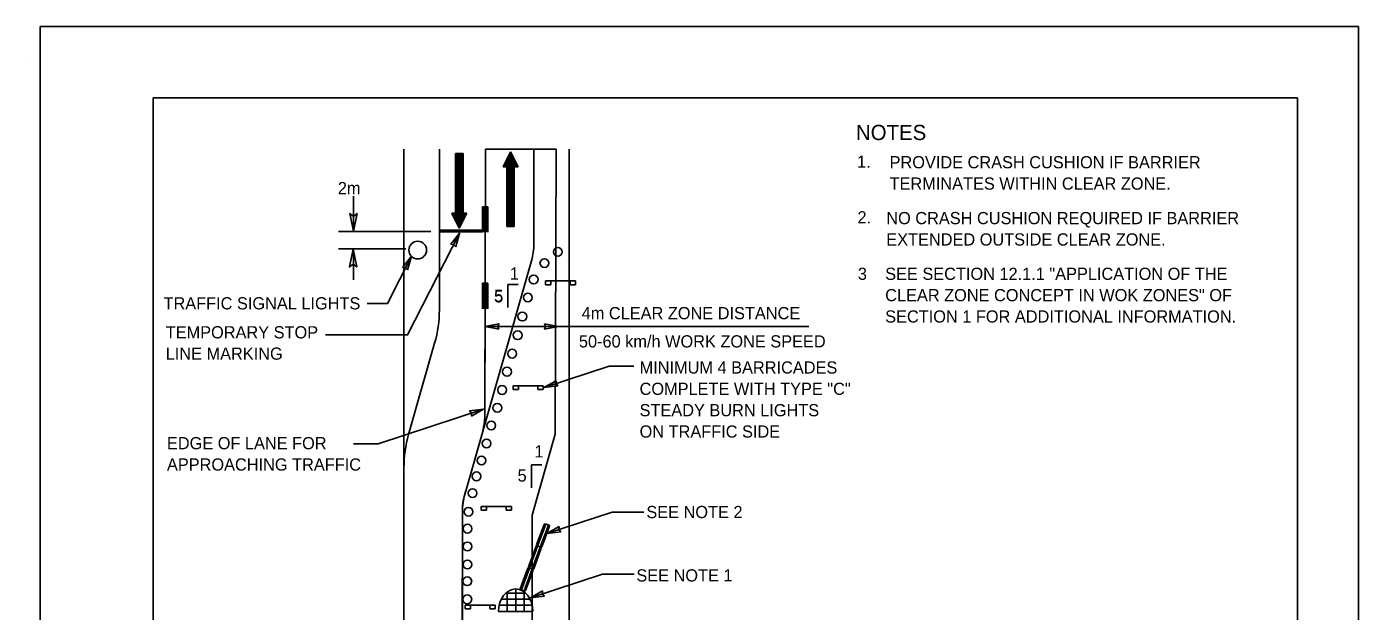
# Model space of a CAD drawing. Extents: x 2427 to 2645, y -255 to 24.
# Drawn here: x 2426.8 to 2645, y -71.9 to 24 of the extents above; entities that cross this region are included whole.
import ezdxf

# ---------------------------------------------------------------- set-up
doc = ezdxf.new("R2010")
doc.units = 0
for name, color, linetype in [('Level 10', 7, 'Continuous'), ('Level 17', 7, 'Continuous'), ('Level 22', 7, 'Continuous'), ('Level 4', 7, 'Continuous'), ('Level 44', 7, 'Continuous'), ('Level 5', 7, 'Continuous'), ('Level 60', 7, 'Continuous')]:
    doc.layers.add(name, color=color, linetype=linetype)

# ---------------------------------------------------------------- blocks, each defined once
blk = doc.blocks.new('TAH01')
at = {"layer": 'Level 5'}
blk.add_lwpolyline([(0, 0), (-3, -0.62), (-2.504, 0), (-3, 0.62)], close=True, dxfattribs=at)
blk = doc.blocks.new('LT1')
at = {"layer": 'Level 5'}
blk.add_blockref('TAH01', (0, 0), dxfattribs=at)
blk = doc.blocks.new('arrow')
at = {"layer": 'Level 60'}
blk.add_lwpolyline([(0.6, 0.12), (0, 0), (0.6, -0.12), (0.56, 0)], close=True, dxfattribs=at)

msp = doc.modelspace()

# ---------------------------------------------------------------- linework, layer by layer
at = {"layer": 'Level 10'}
for p, q in [((2488.59, 3.9), (2488.59, -74.14)), ((2494.4, 3.9), (2494.4, -22.41)), ((2497.05, -6.58), (2497.05, 3.23)), ((2497.05, 3.23), (2498.28, 3.23)), ((2497.05, -7.81), (2497.05, 3.23)), ((2497.21, -8.12), (2497.21, 3.23)), ((2497.36, -8.42), (2497.36, 3.23)), ((2497.52, -8.73), (2497.52, 3.23)), ((2497.67, -9.04), (2497.67, 3.23)), ((2497.82, -8.73), (2497.82, 3.23)), ((2497.97, -8.42), (2497.97, 3.23)), ((2498.13, -8.12), (2498.13, 3.23)), ((2498.28, -6.58), (2498.28, 3.23)), ((2498.28, -7.81), (2498.28, 3.23)), ((2506.06, 3.5), (2504.84, 1.05)), ((2505.45, 2.28), (2505.45, -8.77)), ((2505.61, 2.58), (2505.61, -8.77)), ((2505.76, 2.89), (2505.76, -8.77)), ((2505.91, 3.19), (2505.91, -8.77)), ((2506.06, 3.5), (2506.06, -8.77)), ((2506.06, 3.5), (2507.29, 1.05)), ((2506.22, 3.19), (2506.22, -8.77)), ((2506.37, 2.89), (2506.37, -8.77)), ((2506.53, 2.58), (2506.53, -8.77)), ((2506.68, 2.28), (2506.68, -8.77)), ((2509.88, 3.9), (2509.88, -11.62)), ((2515.69, 3.9), (2515.69, -98.92)), ((2505.45, 1.05), (2504.84, 1.05)), ((2504.99, 1.35), (2504.99, 1.05)), ((2505.15, 1.66), (2505.15, 1.05)), ((2505.3, 1.97), (2505.3, 1.05)), ((2505.45, 1.05), (2505.45, -8.77)), ((2506.68, 1.05), (2506.68, -8.77)), ((2507.29, 1.05), (2506.68, 1.05)), ((2506.83, 1.97), (2506.83, 1.05)), ((2506.99, 1.66), (2506.99, 1.05)), ((2507.14, 1.35), (2507.14, 1.05)), ((2480.31, -3.77), (2480.31, -9.53)), ((2497.67, -9.04), (2496.44, -6.58)), ((2496.44, -6.58), (2497.05, -6.58)), ((2496.59, -6.89), (2496.59, -6.58)), ((2496.75, -7.2), (2496.75, -6.58)), ((2496.9, -7.5), (2496.9, -6.58)), ((2497.67, -9.04), (2498.89, -6.58)), ((2498.28, -6.58), (2498.89, -6.58)), ((2498.43, -7.5), (2498.43, -6.58)), ((2498.59, -7.2), (2498.59, -6.58)), ((2498.74, -6.89), (2498.74, -6.58)), ((2493.03, -9.56), (2477.87, -9.56)), ((2494.4, -9.35), (2501.48, -9.35)), ((2494.4, -9.45), (2501.48, -9.45)), ((2494.4, -9.45), (2501.48, -9.45)), ((2494.4, -9.55), (2501.48, -9.55)), ((2494.4, -9.55), (2501.48, -9.55)), ((2494.4, -9.55), (2501.48, -9.55)), ((2494.4, -9.64), (2501.48, -9.64)), ((2494.4, -9.64), (2501.48, -9.64)), ((2506.68, -8.77), (2505.45, -8.77)), ((2488.92, -12.43), (2477.87, -12.43)), ((2480.31, -12.6), (2480.31, -17.5)), ((2509.5, -14.36), (2498.57, -52.7)), ((2501.86, -39.8), (2501.9, -22.24)), ((2493.63, -27.89), (2489.37, -42.86)), ((2498.79, -51.93), (2501.47, -42.52)), ((2513.4, -42.82), (2509.61, -56.11)), ((2488.6, -172.56), (2488.6, -48.35)), ((2498.24, -172.68), (2498.19, -55.44))]:
    msp.add_line(p, q, dxfattribs=at)
for points in [[(2501.97, 3.9), (2513.52, 3.9), (2513.4, -42.82), (2509.61, -56.11), (2509.63, -98.92), (2498.08, -98.91), (2498.19, -55.44)], [(2501.47, -42.52), (2501.79, -40.85), (2501.86, -39.8), (2501.97, 3.9)]]:
    msp.add_lwpolyline(points, dxfattribs=at)
for centre in [(2513.82, -12.91), (2511.61, -14.76), (2509.85, -17.45), (2508.9, -20.41), (2508, -23.53), (2507.23, -26.59), (2506.33, -29.61), (2505.49, -32.56), (2504.68, -35.57), (2503.9, -38.48), (2502.91, -41.39), (2502.14, -44.33), (2501.3, -47.12), (2500.48, -49.72), (2499.85, -52.47), (2499.17, -55.52), (2499.01, -58.3), (2499, -61.21), (2499, -64.17), (2498.98, -66.92), (2498.98, -69.88)]:
    msp.add_circle(centre, 0.718, dxfattribs=at)
for centre, radius, start, end in [((2499.88, -11.62), 10, 344.0903, 0), ((2474.4, -22.41), 20, 344.0903, 360), ((2491.86, -39.78), 10, 344.0903, 359.8496), ((2508.6, -48.35), 20, 164.0903, 180), ((2507.62, -55.25), 9.43, 159.4198, 181.1903), ((2508.19, -55.44), 10, 164.0903, 180.023)]:
    msp.add_arc(centre, radius, start, end, dxfattribs=at)
at = {"layer": 'Level 17'}
for p, q in [((2428.98, 24.01), (2644.98, 24.01)), ((2428.98, -254.99), (2428.98, 24.01)), ((2644.98, 24.01), (2644.98, -254.99))]:
    msp.add_line(p, q, dxfattribs=at)
at = {"layer": 'Level 22'}
for p, q in [((2447.52, 12.32), (2447.52, -244.18)), ((2447.52, 12.32), (2634.98, 12.32)), ((2634.98, 12.32), (2634.98, -244.18))]:
    msp.add_line(p, q, dxfattribs=at)
at = {"layer": 'Level 4'}
for p, q in [((2511.58, -57.6), (2510.34, -60.95)), ((2510.51, -61.15), (2511.84, -57.55)), ((2510.94, -61.31), (2512.27, -57.71)), ((2511.2, -61.27), (2512.44, -57.91)), ((2511.75, -57.52), (2511.58, -57.6)), ((2512.37, -57.75), (2511.75, -57.52)), ((2512.44, -57.91), (2512.37, -57.75)), ((2510.34, -60.95), (2510.41, -61.12)), ((2510.24, -61.19), (2509, -64.55)), ((2509.18, -64.75), (2510.51, -61.15)), ((2509.61, -64.91), (2510.94, -61.31)), ((2509.87, -64.87), (2511.11, -61.51)), ((2510.41, -61.12), (2510.24, -61.19)), ((2511.03, -61.35), (2510.41, -61.12)), ((2510.41, -61.12), (2511.04, -61.34)), ((2511.11, -61.51), (2511.03, -61.35)), ((2511.2, -61.27), (2511.04, -61.34)), ((2508.91, -64.79), (2507.67, -68.15)), ((2507.84, -68.35), (2509.17, -64.75)), ((2508.28, -68.51), (2509.6, -64.91)), ((2508.54, -68.46), (2509.78, -65.11)), ((2509.08, -64.71), (2508.91, -64.79)), ((2509, -64.55), (2509.08, -64.71)), ((2509.7, -64.94), (2509.08, -64.71)), ((2509.08, -64.71), (2509.7, -64.94)), ((2509.87, -64.87), (2509.7, -64.94)), ((2509.78, -65.11), (2509.7, -64.94)), ((2505.29, -68.86), (2508.54, -68.86)), ((2505.52, -71.86), (2505.52, -68.67)), ((2506.92, -71.86), (2506.92, -68.18)), ((2507.67, -68.15), (2507.75, -68.31)), ((2507.75, -68.31), (2508.37, -68.54)), ((2508.32, -71.86), (2508.32, -68.67)), ((2508.54, -68.46), (2508.37, -68.54)), ((2504.11, -71.86), (2509.72, -71.86)), ((2504.22, -70.86), (2509.62, -70.86)), ((2504.56, -69.86), (2509.27, -69.86))]:
    msp.add_line(p, q, dxfattribs=at)
msp.add_ellipse((2506.92, -71.88), major_axis=(0, 3.7), ratio=0.758621, start_param=4.716532, end_param=7.849839, dxfattribs=at)
at = {"layer": 'Level 44'}
for p, q in [((2502.35, -5.51), (2501.48, -5.51)), ((2502.35, -18.07), (2501.48, -18.07))]:
    msp.add_line(p, q, dxfattribs=at)
for points in [[(2501.48, -9.7), (2501.48, -5.51)], [(2501.63, -9.7), (2501.63, -5.51)], [(2501.77, -9.7), (2501.77, -5.51)], [(2501.92, -9.7), (2501.92, -5.51)], [(2502.06, -9.7), (2502.06, -5.51)], [(2502.21, -9.7), (2502.21, -5.51)], [(2502.35, -9.7), (2502.35, -5.51)], [(2501.48, -22.25), (2501.48, -18.07)], [(2501.63, -22.25), (2501.63, -18.07)], [(2501.77, -22.25), (2501.77, -18.07)], [(2501.92, -22.25), (2501.92, -18.07)], [(2502.06, -22.25), (2502.06, -18.07)], [(2502.21, -22.25), (2502.21, -18.07)], [(2502.35, -22.25), (2502.35, -18.07)]]:
    msp.add_lwpolyline(points, dxfattribs=at)
msp.add_circle((2490.86, -12.62), 1.45, dxfattribs=at)
at = {"layer": 'Level 5'}
for p, q in [((2426.78, 19.01), (2426.78, 19.01)), ((2513.4, -42.82), (2513.52, 3.9)), ((2505.63, -22.05), (2505.63, -18.29)), ((2505.63, -18.29), (2507.34, -18.29)), ((2516.72, -17.69), (2511.8, -17.69)), ((2511.8, -17.69), (2511.8, -18.3)), ((2511.8, -18.3), (2512.67, -18.3)), ((2512.67, -18.3), (2512.67, -17.69)), ((2515.85, -17.69), (2515.85, -18.3)), ((2515.85, -18.3), (2516.72, -18.3)), ((2516.72, -18.3), (2516.72, -17.69)), ((2501.9, -25.14), (2554.93, -25.14)), ((2522.24, -31.67), (2511.55, -35.18)), ((2526.28, -31.67), (2522.24, -31.67)), ((2511.42, -34.86), (2506.5, -34.86)), ((2506.5, -34.86), (2506.5, -35.47)), ((2507.37, -35.47), (2507.37, -34.86)), ((2510.55, -34.86), (2510.55, -35.47)), ((2511.42, -35.47), (2511.42, -34.86)), ((2506.5, -35.47), (2507.37, -35.47)), ((2510.55, -35.47), (2511.42, -35.47)), ((2484.36, -44.4), (2480.32, -44.4)), ((2509.48, -51.59), (2509.48, -47.83)), ((2509.48, -47.83), (2511.19, -47.83)), ((2506.21, -54.64), (2501.28, -54.64)), ((2501.28, -54.64), (2501.28, -55.25)), ((2501.28, -55.25), (2502.15, -55.25)), ((2502.15, -55.25), (2502.15, -54.64)), ((2505.33, -54.64), (2505.33, -55.25)), ((2505.33, -55.25), (2506.21, -55.25)), ((2506.21, -55.25), (2506.21, -54.64)), ((2509.63, -98.92), (2509.61, -56.11)), ((2522.71, -55.57), (2512.01, -59.08)), ((2527.88, -55.57), (2522.71, -55.57)), ((2521.16, -65.76), (2509.32, -69.64)), ((2526.34, -65.76), (2521.16, -65.76)), ((2503.56, -70.82), (2498.63, -70.82)), ((2498.63, -70.82), (2498.63, -71.43)), ((2498.63, -71.43), (2499.51, -71.43)), ((2499.51, -71.43), (2499.51, -70.82)), ((2502.69, -70.82), (2502.69, -71.43)), ((2502.69, -71.43), (2503.56, -71.43)), ((2503.56, -71.43), (2503.56, -70.82))]:
    msp.add_line(p, q, dxfattribs=at)
for points in [[(2475.75, -26.54), (2489.2, -26.54), (2497.71, -9.87)], [(2482.58, -21.36), (2485.89, -21.36), (2489.83, -13.64)], [(2484.36, -44.4), (2501.64, -38.7)]]:
    msp.add_lwpolyline(points, dxfattribs=at)

# ---------------------------------------------------------------- block references
for name, p, xscale, yscale, rotation in [('LT1', (2480.31, -9.53), 0.9676, -0.9676, -90), ('arrow', (2497.71, -9.87), 3.750000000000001, 3.7500000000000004, -117.06329479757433), ('LT1', (2480.26, -12.49), 0.9676, -0.9676, 90), ('arrow', (2489.83, -13.64), 3.750000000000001, 3.7500000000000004, -117.06329479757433), ('arrow', (2513.9, -25.14), 3.75, -3.75, 180), ('arrow', (2511.53, -35.17), 3.7500000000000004, 3.7499999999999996, 18.145578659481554), ('arrow', (2501.64, -38.7), 3.7500000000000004, 3.7500000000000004, -161.77115021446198), ('arrow', (2512.01, -59.08), 3.7500000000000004, 3.7499999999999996, 18.145578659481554), ('arrow', (2509.31, -69.63), 3.7500000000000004, 3.7499999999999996, 18.145578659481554)]:
    msp.add_blockref(name, p, dxfattribs=dict(at, xscale=xscale, yscale=yscale, rotation=rotation))
at = {"layer": 'Level 5', "xscale": 3.75, "yscale": -3.75}
msp.add_blockref('arrow', (2501.9, -25.14), dxfattribs=at)

# ---------------------------------------------------------------- texts
at = {"layer": 'Level 5'}
for s, height, p in [('NOTES', 2.5, (2562.66, 5.41)), ('1.', 2, (2562.84, 0.87)), ('PROVIDE CRASH CUSHION IF BARRIER', 2, (2568.17, 0.78)), ('2m', 2, (2477.77, -3.46)), ('TERMINATES WITHIN CLEAR ZONE.', 2, (2568.17, -2.72)), ('2.', 2, (2562.91, -8.25)), ('NO CRASH CUSHION REQUIRED IF BARRIER', 2, (2567.63, -8.38)), ('EXTENDED OUTSIDE CLEAR ZONE.', 2, (2567.63, -11.88)), ('1', 2, (2505.95, -17.46)), ('3', 2, (2562.97, -17.51)), ('SEE SECTION 12.1.1 "APPLICATION OF THE', 2, (2567.45, -17.51)), ('5', 2, (2503.36, -21.11)), ('CLEAR ZONE CONCEPT IN WOK ZONES" OF', 2, (2567.45, -21.01)), ('TRAFFIC SIGNAL LIGHTS', 2, (2449.21, -22.35)), ('SECTION 1 FOR ADDITIONAL INFORMATION.', 2, (2567.45, -24.51)), ('TEMPORARY STOP', 2, (2449.57, -27.1)), ('50-60 km/h WORK ZONE SPEED', 2, (2517.27, -28.59)), ('LINE MARKING', 2, (2449.57, -30.6)), ('MINIMUM 4 BARRICADES', 2, (2527.21, -32.87)), ('COMPLETE WITH TYPE "C" ', 2, (2527.21, -36.37)), ('STEADY BURN LIGHTS', 2, (2527.21, -39.87)), ('ON TRAFFIC SIDE', 2, (2527.21, -43.37)), ('EDGE OF LANE FOR', 2, (2449.77, -45.28)), ('1', 2, (2509.99, -46.63)), ('APPROACHING TRAFFIC', 2, (2449.77, -48.78)), ('5', 2, (2507.22, -50.58)), ('SEE NOTE 2', 2, (2528.32, -56.57)), ('SEE NOTE 1', 2, (2526.68, -66.96))]:
    msp.add_text(s, height=height, dxfattribs=at).set_placement(p)
for s, p in [('5', (2503.39, -21.21)), ('4m CLEAR ZONE DISTANCE', (2517.72, -23.96))]:
    msp.add_text(s, height=2, rotation=360, dxfattribs=at).set_placement(p)

doc.saveas('drawing.dxf')
